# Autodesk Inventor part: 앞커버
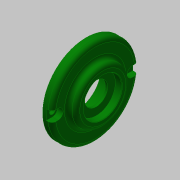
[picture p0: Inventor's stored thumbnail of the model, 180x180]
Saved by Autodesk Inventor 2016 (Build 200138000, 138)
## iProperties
Created: 2019-06
Part Number: 앞커버
Material: 알루미늄 6061
Document SubType Name: Modeling
Designer: mduedu
Density: 2.71 g/cm^3
Appearance: 진녹색
Mass: 83.0118 g
Surface Area: 113.274 cm^2
Volume: 30.6317 cm^3
Author: mduedu
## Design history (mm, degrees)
sketch "스케치1"
  geometry: L1 (0, 0)-(7, 0); L2 (7, 0)-(7, 25); L3 (7, 25)-(0, 25); L4 (0, 25)-(0, 0); L5 (7, 0)-(14, 0); L6 (14, 0)-(14, 34); L7 (14, 34)-(7, 34); L8 (7, 34)-(7, 0); L9 (14, 0)-(20, 0); L10 (20, 0)-(20, 21); L11 (20, 21)-(14, 21); L12 (14, 21)-(14, 0)
  constraints: 24 end point, 6 parallel, 3 horizontal, 3 perpendicular
  dimensions: "d0" = 20 distance between parallel lines of L10 L4; "d2" = 7 distance of L2.end L3.end; "d3" = 7 distance of L6.end L7.end; "d4" = 50 diameter of L3 L1; "d5" = 68 diameter of L7 L5; "d6" = 42 diameter of L11 L9
revolve "회전1" sketch "스케치1" stored, may be unused: angle "d7" = 90 deg
sketch "스케치2"
  geometry: L1 (0, -25)-(0, 25) reference; L2 (0, 25)-(7, 25) reference; L3 (7, 25)-(7, 34) reference; L4 (7, 34)-(14, 34) reference; L5 (14, 34)-(14, 21) reference; L6 (14, 21)-(20, 21) reference; L7 (20, 21)-(20, -21) reference; L8 (20, -21)-(14, -21) reference; L9 (14, -21)-(14, -34) reference; L10 (14, -34)-(7, -34) reference; L11 (7, -34)-(7, -25) reference; L12 (7, -25)-(0, -25) reference; L13 (10, 0)-(10, 17.5); L14 (10, 17.5)-(0, 17.5); L15 (0, 17.5)-(0, 0); L16 (13, 0)-(13, 15); L17 (13, 15)-(10, 15); L18 (10, 15)-(10, 0); L19 (14.8, 0)-(14.8, 9); L20 (14.8, 9)-(13, 9); L21 (13, 9)-(13, 0); L22 (20, 0)-(20, 15); L23 (20, 15)-(14.8, 15); L24 (14.8, 15)-(14.8, 0)
  constraints: 24 end point, 4 horizontal, 4 horizontal alignment, 4 parallel, 4 vertical, 1 point on line, 8 other
  dimensions: "d8" = 35 dimension on L14; "d10" = 30 dimension on L17; "d11" = 18 dimension on L20; "d12" = 30 dimension on L23; "d13" = 10 distance of L13.end L14.end; "d14" = 3 distance of L16.end L17.end; "d15" = 5.2 distance of L22.end L23.end
revolve "회전2" sketch "스케치2" stored, may be unused: angle "d16" = 90 deg
chamfer "모따기1" distance "d18" = 0.5; stored, may be unused: second distance "d19" = 2, angle "d20" = 30 deg
fillet "모깎기2" dims "d21" = 0.3
fillet "모깎기3" dims "d22" = 3
chamfer "모따기2" distance "d23" = 1; stored, may be unused: second distance "d24" = 2, angle "d25" = 30 deg
fillet "모깎기4" dims "d26" = 3
sketch "스케치3" dims "d27" = 58
  geometry: L1 (-4, 29)-(-4, 33.764); L2 (4, 33.764)-(4, 29); A1 r 4 centre (0, 29) between (-4, 29) and (4, 29); A2 r 34 centre (0, 0) between (4, 33.764) and (-4, 33.764); A3 r 34 centre (0, 0) between (4, 33.764) and (-4, 33.764) reference; 3 further points
  constraints: 6 point on circle, 4 end point, 3 coincident, 2 centre point, 2 tangent, 2 vertical, 2 vertical alignment, 1 concentric, 2 other
  dimensions: "d28" = 8 diameter of A1
extrude "돌출1" cut sketch "스케치3" distance "d29" = 4.4; taper "d30" = 0 deg
sketch "스케치4"
  geometry: A1 r 4 centre (0, 29) between (-4, 29) and (4, 29) reference; 2 further points
  constraints: 1 coincident
hole "구멍1" sketch "스케치4" at (0, 29) diameter "d34" = 4.5; stored, may be unused: countersink angle "d38" = 90 deg, drill point angle "d40" = 118 deg; dims "d35" = 6, "d36" = 4, "d37" = 2, "d39" = 8
node "솔리드1"
pattern_circular "원형 패턴1" dims angle "d32" = 360 deg
pattern_circular "원형 패턴2" dims angle "d42" = 360 deg
node "절단 모서리 투영1"
